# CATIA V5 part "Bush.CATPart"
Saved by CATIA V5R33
Part number: Bush
Bounding box of the stored display mesh (mm): x 75 to 115, y 10 to 50, z 160 to 220
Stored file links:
  D:\PROJECTS\Project 2023\CATIA V5 6R 2023\Resources\Tutorial Files\c12_catia_v5_6r2023_tut\c12tut2\Bush.CATPart
  E:\_Deepak\2017_Deepak\CATIA\Resources\Tutorial Files\Tutorials\c12_catia_v5_6r2015_tut\c12tut2\Assembly_cat_v5-6r2016.CATProduct
  D:\PROJECTS\Project 2021\US EDITION\CATIA V5 6R 2021\Resources\Tutorial Files\c12_catia_v5_6r2021_tut\c12tut2\Guide Pillar.CATPart
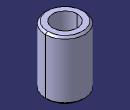
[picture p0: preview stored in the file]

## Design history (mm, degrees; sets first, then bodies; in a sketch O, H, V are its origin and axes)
Set1
  DatumSurface1: linked copy from another document
  DatumCurve1: linked copy from another document
Body1 (main body)
  Sketch1 on face of DatumSurface1, origin (0, 0, 200), H (1, 0, 0), V (0, 1, 0)
    projected circle E1 centre (95, 30) radius 12.5 from edge of DatumCurve1
    circle A1 centre (95, 30) radius 20
    point P1 (95, 30)
    radius A1 = 20
    concentricity: P1 E1, A1 E1
  Pad1: profile Sketch1, direction (0, 0, 1), length 20, opposite side length 40
  Chamfer1: length 2, angle 45, on face of Pad1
